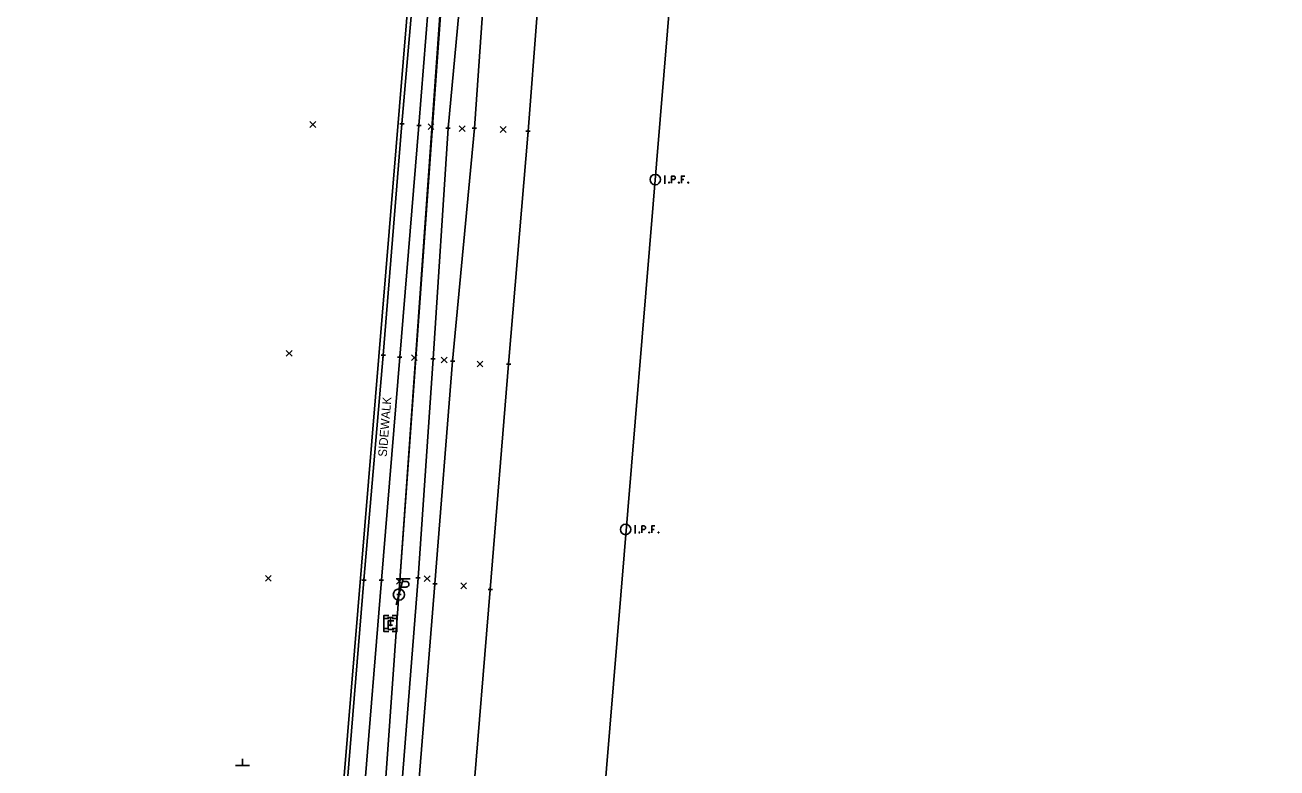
# Model space of a CAD drawing. Extents: x 1380550 to 1381945, y 468927 to 470496.
# Drawn here: x 1381495.3 to 1381783.2, y 469978.3 to 470149.2 of the extents above; entities that cross this region are included whole.
import ezdxf

# ---------------------------------------------------------------- set-up
doc = ezdxf.new("R2010")
doc.units = 0
for name, color, linetype in [('DR_X_Ditch', 7, 'Continuous'), ('PV_X_COP', 7, 'Continuous'), ('PV_X_EOP', 7, 'Continuous'), ('PV_X_Walk', 7, 'Continuous'), ('RD_X_Text', 7, 'Continuous'), ('RW_X_Esmt_General', 7, 'Continuous'), ('SN_X_Public', 7, 'Continuous'), ('SV_X_Mon_Cells_Found', 7, 'Continuous'), ('SV_X_Random_Point', 7, 'Continuous'), ('SV_X_Shot_Marker', 7, 'Continuous'), ('UT_X_Electric', 7, 'Continuous'), ('UT_X_Electric_Cells', 7, 'Continuous'), ('UT_X_Misc_Cells', 7, 'Continuous'), ('UT_X_Telecom', 7, 'Continuous'), ('UT_X_Telecom_Cells', 7, 'Continuous')]:
    doc.layers.add(name, color=color, linetype=linetype)

msp = doc.modelspace()

# ---------------------------------------------------------------- linework, layer by layer
at = {"layer": 'DR_X_Ditch'}
msp.add_lwpolyline([(1381599.49, 470202.78), (1381597.12, 470179.51), (1381597.25, 470175.53), (1381597.2, 470175.03), (1381592.57, 470125.52), (1381589.1, 470072.43), (1381585.65, 470022.01), (1381581.71, 469971.4), (1381577.66, 469928.75), (1381573.1, 469880.44), (1381570.64, 469867.29)], dxfattribs=at)
at = {"layer": 'PV_X_COP'}
msp.add_lwpolyline([(1381627.41, 470324.23), (1381625.02, 470294.42), (1381622.34, 470259.95), (1381618.76, 470220.14), (1381616.92, 470200.19), (1381615.1, 470178.83), (1381610.95, 470124.78), (1381606.49, 470071.23), (1381602.26, 470019.36), (1381598.18, 469969.8), (1381595.01, 469928.06), (1381590.91, 469878.81), (1381589.36, 469859.11), (1381585.99, 469815.58), (1381581.29, 469760.78)], dxfattribs=at)
at = {"layer": 'PV_X_EOP'}
msp.add_lwpolyline([(1381575.39, 470244.04), (1381576.99, 470244.17), (1381579.54, 470245.54), (1381580.63, 470247.96), (1381580.96, 470249.54), (1381591.47, 470243.59), (1381595.25, 470241), (1381599.72, 470235.67), (1381603.29, 470229.19), (1381604.88, 470222.31), (1381604.1, 470201.73), (1381602.36, 470179.43), (1381598.63, 470125.51), (1381593.59, 470071.89), (1381589.53, 470020.65), (1381585.49, 469971.09), (1381582.04, 469928.84), (1381578.38, 469880.28), (1381576.86, 469862.02), (1381576.83, 469860.71), (1381576.16, 469857.38), (1381571.59, 469847.12), (1381563.14, 469838.25)], dxfattribs=at)
at = {"layer": 'PV_X_Walk'}
for points in [[(1381595.25, 470241), (1381595.01, 470239.38), (1381594.79, 470235.56), (1381591.94, 470203.13), (1381590.15, 470180.15), (1381585.84, 470126.11), (1381581.45, 470072.84), (1381577.22, 470021.47), (1381573.16, 469971.68), (1381569.7, 469929.43), (1381565.6, 469880.89), (1381564.41, 469867), (1381562.95, 469848.39), (1381561.9, 469840.88)], [(1381542.56, 470237.64), (1381568.34, 470236.69), (1381578.51, 470236.26), (1381584.49, 470236.02), (1381590.64, 470235.62), (1381587.95, 470203.42), (1381586.62, 470180.46), (1381581.93, 470126.46), (1381577.65, 470073.24), (1381573.2, 470021.54), (1381569.15, 469971.74), (1381565.64, 469929.65), (1381561.64, 469881.16), (1381560.46, 469867.32), (1381559.27, 469848.71), (1381558.35, 469840.14)]]:
    msp.add_lwpolyline(points, dxfattribs=at)
at = {"layer": 'RW_X_Esmt_General'}
for points in [[(1381490.4, 469029.46), (1381590.2, 470237.18), (1380558.69, 470277.03)], [(1381783.19, 470213.89), (1381648.78, 470217.49), (1381563.79, 469189.03)]]:
    msp.add_lwpolyline(points, dxfattribs=at)
at = {"layer": 'SN_X_Public'}
for p, q in [((1381546.9, 469978.84), (1381543.7, 469978.84)), ((1381545.3, 469978.84), (1381545.3, 469980.44))]:
    msp.add_line(p, q, dxfattribs=at)
at = {"layer": 'SV_X_Mon_Cells_Found'}
for points in [[(1381642.23, 470114.45), (1381642.59, 470114.45)], [(1381642.41, 470112.85), (1381642.41, 470114.45)], [(1381643.97, 470112.85), (1381643.97, 470114.45), (1381644.5, 470114.45), (1381644.56, 470114.44), (1381644.64, 470114.41), (1381644.67, 470114.39), (1381644.7, 470114.36), (1381644.75, 470114.3), (1381644.78, 470114.24), (1381644.8, 470114.14), (1381644.8, 470113.98), (1381644.79, 470113.93), (1381644.77, 470113.86), (1381644.72, 470113.77), (1381644.68, 470113.73), (1381644.65, 470113.71), (1381644.59, 470113.68), (1381644.5, 470113.67), (1381643.97, 470113.67)], [(1381646.98, 470114.45), (1381646.22, 470114.45), (1381646.22, 470112.85)], [(1381642.23, 470112.85), (1381642.59, 470112.85)], [(1381643.37, 470113.06), (1381643.42, 470113.06), (1381643.46, 470113.04), (1381643.49, 470112.99), (1381643.49, 470112.93), (1381643.46, 470112.88), (1381643.42, 470112.85), (1381643.37, 470112.85), (1381643.33, 470112.88), (1381643.3, 470112.93), (1381643.3, 470112.99), (1381643.33, 470113.04), (1381643.37, 470113.06)], [(1381645.62, 470113.06), (1381645.67, 470113.06), (1381645.7, 470113.04), (1381645.74, 470112.99), (1381645.74, 470112.93), (1381645.7, 470112.88), (1381645.67, 470112.85), (1381645.62, 470112.85), (1381645.58, 470112.88), (1381645.55, 470112.93), (1381645.55, 470112.99), (1381645.58, 470113.04), (1381645.62, 470113.06)], [(1381646.22, 470113.67), (1381646.76, 470113.67)], [(1381647.77, 470113.06), (1381647.82, 470113.06), (1381647.85, 470113.04), (1381647.89, 470112.99), (1381647.89, 470112.93), (1381647.85, 470112.88), (1381647.82, 470112.85), (1381647.77, 470112.85), (1381647.73, 470112.88), (1381647.7, 470112.93), (1381647.7, 470112.99), (1381647.73, 470113.04), (1381647.77, 470113.06)], [(1381635.4, 470033.97), (1381635.75, 470033.97)], [(1381635.57, 470032.37), (1381635.57, 470033.97)], [(1381637.14, 470032.37), (1381637.14, 470033.97), (1381637.67, 470033.97), (1381637.72, 470033.95), (1381637.8, 470033.93), (1381637.83, 470033.9), (1381637.87, 470033.88), (1381637.91, 470033.81), (1381637.94, 470033.75), (1381637.96, 470033.65), (1381637.96, 470033.5), (1381637.95, 470033.45), (1381637.93, 470033.37), (1381637.89, 470033.28), (1381637.84, 470033.25), (1381637.81, 470033.22), (1381637.76, 470033.2), (1381637.67, 470033.18), (1381637.14, 470033.18)], [(1381640.15, 470033.97), (1381639.39, 470033.97), (1381639.39, 470032.37)], [(1381639.39, 470033.18), (1381639.93, 470033.18)], [(1381635.4, 470032.37), (1381635.75, 470032.37)], [(1381636.53, 470032.58), (1381636.59, 470032.58), (1381636.62, 470032.55), (1381636.65, 470032.5), (1381636.65, 470032.44), (1381636.62, 470032.39), (1381636.59, 470032.37), (1381636.53, 470032.37), (1381636.5, 470032.39), (1381636.47, 470032.44), (1381636.47, 470032.5), (1381636.5, 470032.55), (1381636.53, 470032.58)], [(1381638.78, 470032.58), (1381638.84, 470032.58), (1381638.87, 470032.55), (1381638.9, 470032.5), (1381638.9, 470032.44), (1381638.87, 470032.39), (1381638.84, 470032.37), (1381638.78, 470032.37), (1381638.75, 470032.39), (1381638.71, 470032.44), (1381638.71, 470032.5), (1381638.75, 470032.55), (1381638.78, 470032.58)], [(1381640.93, 470032.58), (1381640.98, 470032.58), (1381641.02, 470032.55), (1381641.05, 470032.5), (1381641.05, 470032.44), (1381641.02, 470032.39), (1381640.98, 470032.37), (1381640.93, 470032.37), (1381640.9, 470032.39), (1381640.86, 470032.44), (1381640.86, 470032.5), (1381640.9, 470032.55), (1381640.93, 470032.58)]]:
    msp.add_lwpolyline(points, dxfattribs=at)
for centre in [(1381640.22, 470113.65), (1381633.38, 470033.17)]:
    msp.add_circle(centre, 1.2, dxfattribs=at)
at = {"layer": 'SV_X_Random_Point'}
for p, q in [((1381560.78, 470125.68), (1381562.12, 470127.02)), ((1381560.78, 470127.02), (1381562.12, 470125.68)), ((1381587.99, 470125.16), (1381589.32, 470126.49)), ((1381587.99, 470126.49), (1381589.32, 470125.16)), ((1381595.13, 470124.71), (1381596.47, 470126.05)), ((1381595.13, 470126.05), (1381596.47, 470124.71)), ((1381604.57, 470124.51), (1381605.91, 470125.85)), ((1381604.57, 470125.85), (1381605.91, 470124.51)), ((1381555.34, 470073.03), (1381556.68, 470074.37)), ((1381555.34, 470074.37), (1381556.68, 470073.03)), ((1381584.13, 470072.03), (1381585.46, 470073.37)), ((1381584.13, 470073.37), (1381585.46, 470072.03)), ((1381591, 470071.5), (1381592.33, 470072.83)), ((1381591, 470072.83), (1381592.33, 470071.5)), ((1381599.22, 470070.57), (1381600.56, 470071.9)), ((1381599.22, 470071.9), (1381600.56, 470070.57)), ((1381550.55, 470021.28), (1381551.88, 470022.61)), ((1381550.55, 470022.61), (1381551.88, 470021.28)), ((1381580.68, 470020.59), (1381582.01, 470021.92)), ((1381580.68, 470021.92), (1381582.01, 470020.59)), ((1381587.09, 470021.17), (1381588.43, 470022.51)), ((1381587.09, 470022.51), (1381588.43, 470021.17)), ((1381595.47, 470019.55), (1381596.81, 470020.89)), ((1381595.47, 470020.89), (1381596.81, 470019.55))]:
    msp.add_line(p, q, dxfattribs=at)
at = {"layer": 'SV_X_Shot_Marker'}
for p, q in [((1381581.43, 470126.46), (1381582.43, 470126.46)), ((1381581.93, 470126.96), (1381581.93, 470125.96)), ((1381581.93, 470126.46), (1381581.93, 470126.46)), ((1381585.34, 470126.11), (1381586.34, 470126.11)), ((1381585.84, 470126.61), (1381585.84, 470125.61)), ((1381585.84, 470126.11), (1381585.84, 470126.11)), ((1381592.07, 470125.52), (1381593.07, 470125.52)), ((1381592.57, 470126.02), (1381592.57, 470125.02)), ((1381592.57, 470125.52), (1381592.57, 470125.52)), ((1381598.13, 470125.51), (1381599.13, 470125.51)), ((1381598.63, 470126.01), (1381598.63, 470125.01)), ((1381598.63, 470125.51), (1381598.63, 470125.51)), ((1381610.95, 470125.28), (1381610.95, 470124.28)), ((1381610.45, 470124.78), (1381611.45, 470124.78)), ((1381610.95, 470124.78), (1381610.95, 470124.78)), ((1381577.65, 470073.74), (1381577.65, 470072.74)), ((1381577.15, 470073.24), (1381578.15, 470073.24)), ((1381577.65, 470073.24), (1381577.65, 470073.24)), ((1381580.95, 470072.84), (1381581.95, 470072.84)), ((1381581.45, 470073.34), (1381581.45, 470072.34)), ((1381581.45, 470072.84), (1381581.45, 470072.84)), ((1381588.6, 470072.43), (1381589.6, 470072.43)), ((1381589.1, 470072.93), (1381589.1, 470071.93)), ((1381589.1, 470072.43), (1381589.1, 470072.43)), ((1381593.09, 470071.89), (1381594.09, 470071.89)), ((1381593.59, 470072.39), (1381593.59, 470071.39)), ((1381593.59, 470071.89), (1381593.59, 470071.89)), ((1381605.99, 470071.23), (1381606.99, 470071.23)), ((1381606.49, 470071.73), (1381606.49, 470070.73)), ((1381606.49, 470071.23), (1381606.49, 470071.23)), ((1381573.2, 470022.04), (1381573.2, 470021.04)), ((1381577.22, 470021.97), (1381577.22, 470020.97)), ((1381585.15, 470022.01), (1381586.15, 470022.01)), ((1381585.65, 470022.51), (1381585.65, 470021.51)), ((1381585.65, 470022.01), (1381585.65, 470022.01)), ((1381572.7, 470021.54), (1381573.7, 470021.54)), ((1381573.2, 470021.54), (1381573.2, 470021.54)), ((1381576.72, 470021.47), (1381577.72, 470021.47)), ((1381577.22, 470021.47), (1381577.22, 470021.47)), ((1381581.26, 470018.7), (1381581.26, 470017.7)), ((1381581.26, 470018.7), (1381581.26, 470017.7)), ((1381589.03, 470020.65), (1381590.03, 470020.65)), ((1381589.53, 470021.15), (1381589.53, 470020.15)), ((1381589.53, 470020.65), (1381589.53, 470020.65)), ((1381601.76, 470019.36), (1381602.76, 470019.36)), ((1381602.26, 470019.86), (1381602.26, 470018.86)), ((1381602.26, 470019.36), (1381602.26, 470019.36)), ((1381580.76, 470018.2), (1381581.76, 470018.2)), ((1381580.76, 470018.2), (1381581.76, 470018.2)), ((1381581.26, 470018.2), (1381581.26, 470018.2)), ((1381581.26, 470018.2), (1381581.26, 470018.2))]:
    msp.add_line(p, q, dxfattribs=at)
at = {"layer": 'UT_X_Electric'}
msp.add_lwpolyline([(1381665.56, 470247.4), (1381595.79, 470220.83), (1381581.26, 470018.2), (1381571.97, 469887.64), (1381559.77, 469757.41), (1381543.86, 469565.78), (1381529.17, 469390.12), (1381515.28, 469203.1), (1381540.8, 469054.26)], dxfattribs=at)
at = {"layer": 'UT_X_Electric_Cells'}
for p, q in [((1381578.8, 470011.16), (1381579.8, 470011.16)), ((1381579.3, 470011.16), (1381579.3, 470011.16))]:
    msp.add_line(p, q, dxfattribs=at)
for points in [[(1381578.9, 470012.66), (1381577.8, 470012.66), (1381577.8, 470011.56)], [(1381577.8, 470010.76), (1381577.8, 470009.66), (1381578.9, 470009.66)], [(1381580.05, 470012.16), (1381578.8, 470012.16), (1381578.8, 470010.16), (1381580.05, 470010.16)], [(1381580.8, 470011.56), (1381580.8, 470012.66), (1381579.7, 470012.66)], [(1381579.7, 470009.66), (1381580.8, 470009.66), (1381580.8, 470010.76)]]:
    msp.add_lwpolyline(points, dxfattribs=at)
at = {"layer": 'UT_X_Misc_Cells'}
for p, q in [((1381582.23, 470021.8), (1381580.62, 470015.8)), ((1381583.83, 470021.8), (1381580.63, 470021.8)), ((1381581.73, 470019.92), (1381582.92, 470019.92)), ((1381582.07, 470021.2), (1381582.92, 470021.2))]:
    msp.add_line(p, q, dxfattribs=at)
msp.add_circle((1381581.26, 470018.2), 1.3, dxfattribs=at)
msp.add_arc((1381582.93, 470020.56), 0.638, 268.8767, 91.1233, dxfattribs=at)
at = {"layer": 'UT_X_Telecom'}
msp.add_lwpolyline([(1381665.56, 470247.4), (1381595.35, 470217.51), (1381581.26, 470018.2), (1381571.97, 469887.64), (1381559.77, 469757.41), (1381543.86, 469565.78), (1381529.17, 469390.12), (1381515.28, 469203.1), (1381540.8, 469054.26)], dxfattribs=at)
at = {"layer": 'UT_X_Telecom_Cells'}
for p, q in [((1381578.65, 470012.89), (1381579.95, 470012.89)), ((1381579.3, 470010.89), (1381579.3, 470012.89)), ((1381579.3, 470011.89), (1381579.3, 470011.89))]:
    msp.add_line(p, q, dxfattribs=at)
for points in [[(1381578.9, 470013.39), (1381577.8, 470013.39), (1381577.8, 470012.29)], [(1381580.8, 470012.29), (1381580.8, 470013.39), (1381579.7, 470013.39)], [(1381577.8, 470011.49), (1381577.8, 470010.39), (1381578.9, 470010.39)], [(1381579.7, 470010.39), (1381580.8, 470010.39), (1381580.8, 470011.49)]]:
    msp.add_lwpolyline(points, dxfattribs=at)

# ---------------------------------------------------------------- texts
at = {"layer": 'RD_X_Text'}
msp.add_text('SIDEWALK', height=2, rotation=85.521, dxfattribs=at).set_placement((1381578.45, 470049.83))

doc.saveas('drawing.dxf')
